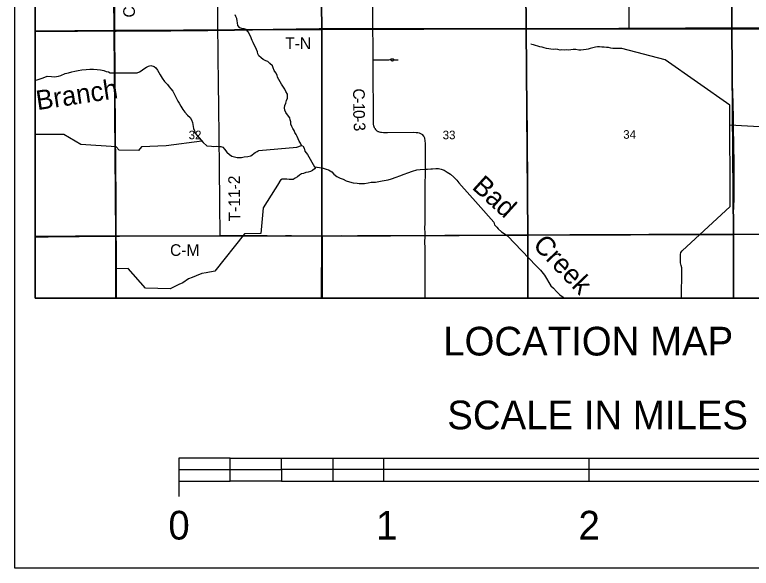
# Model space of a CAD drawing. Extents: x 0 to 34, y 0 to 22.
# Drawn here: x 23.417 to 27.01, y 14 to 16.699 of the extents above; entities that cross this region are included whole.
import ezdxf

# ---------------------------------------------------------------- set-up
doc = ezdxf.new("R2010")
doc.units = 0
for name, color, linetype in [('GM_X_County_Road', 7, 'Continuous'), ('GM_X_County_Road_Text', 7, 'Continuous'), ('GM_X_Minor_River', 7, 'Continuous'), ('GM_X_Minor_River_Text', 7, 'Continuous'), ('GM_X_Section', 7, 'Continuous'), ('GM_X_Section_Text', 7, 'Continuous'), ('GM_X_State_Route', 7, 'Continuous'), ('GM_X_Township_Road', 7, 'Continuous'), ('GM_X_Township_Road_Text', 7, 'Continuous'), ('GM_X_Township_Text', 7, 'Continuous'), ('SC_Scratch1', 7, 'Continuous'), ('SH_Data', 7, 'Continuous'), ('SH_Text', 7, 'Continuous')]:
    doc.layers.add(name, color=color, linetype=linetype)

msp = doc.modelspace()

# ---------------------------------------------------------------- linework, layer by layer
at = {"layer": 'GM_X_County_Road'}
for points in [[(23.9049, 16.6197), (23.9048, 16.6263), (23.9045, 16.6667), (23.903, 16.8346), (23.9026, 16.875), (23.9006, 17.0056), (23.8996, 17.0864), (23.8985, 17.161), (23.8971, 17.2885), (23.897, 17.3071), (23.8967, 17.3289), (23.8966, 17.3475), (23.8962, 17.3693), (23.8954, 17.4253), (23.8947, 17.4905), (23.8933, 17.6149), (23.8934, 17.6243)], [(25.1644, 16.6302), (25.1644, 16.6391), (25.1641, 16.6764), (25.1634, 16.7386), (25.1617, 16.8816), (25.1603, 16.9903), (25.1593, 17.1051), (25.1592, 17.1327), (25.1575, 17.2632), (25.157, 17.2847), (25.1567, 17.3248), (25.1562, 17.3557), (25.1558, 17.3991), (25.1547, 17.5016), (25.1535, 17.6025), (25.1534, 17.6272), (25.1534, 17.6295)], [(23.5167, 16.6173), (23.6476, 16.6186), (23.7222, 16.6189), (23.7998, 16.6205), (23.8216, 16.6207), (23.8778, 16.6199), (23.9049, 16.6197)], [(23.9049, 16.6197), (23.9108, 16.6197), (24.1779, 16.6213), (24.296, 16.6222), (24.3581, 16.6229), (24.4081, 16.6235)], [(23.9119, 15.6196), (23.9116, 15.647), (23.9112, 15.6874), (23.9112, 15.7247), (23.9108, 15.7931), (23.9093, 15.9766), (23.9087, 16.1134), (23.9081, 16.16), (23.9068, 16.3248), (23.9066, 16.3869), (23.9061, 16.446), (23.906, 16.4926), (23.9055, 16.5393), (23.9052, 16.6108), (23.9049, 16.6197)], [(24.4081, 16.6235), (24.4887, 16.6246), (24.5632, 16.6255), (24.7902, 16.6281), (24.9021, 16.6294), (25.0308, 16.6301), (25.034, 16.63), (25.0566, 16.6304), (25.1405, 16.6301), (25.1644, 16.6302)], [(25.1644, 16.6302), (25.2773, 16.6305), (25.3469, 16.6304), (25.4744, 16.6305), (25.6516, 16.6305), (25.7819, 16.6303), (25.8192, 16.63), (25.9122, 16.63)], [(25.1653, 16.4799), (25.1647, 16.5499), (25.1644, 16.6302)], [(25.9122, 16.63), (25.9249, 16.63), (26.1456, 16.6307), (26.1985, 16.6304), (26.3633, 16.6315), (26.4137, 16.6316)], [(26.4137, 16.6316), (26.4752, 16.6318), (26.6897, 16.6328), (26.9163, 16.6335)], [(26.9163, 16.6335), (26.9633, 16.6336), (27.0846, 16.6341), (27.3892, 16.6364), (27.4981, 16.6359), (27.6038, 16.635), (27.7748, 16.6349), (27.8618, 16.6351), (27.9219, 16.634)], [(25.1739, 16.1438), (25.1716, 16.1483), (25.1697, 16.1527), (25.1682, 16.1581), (25.1674, 16.165), (25.167, 16.177), (25.1669, 16.2173), (25.1666, 16.2671), (25.1659, 16.3666), (25.1656, 16.4319), (25.1653, 16.4799)], [(25.1739, 16.1438), (25.1768, 16.1397), (25.1789, 16.1375), (25.1835, 16.1335), (25.186, 16.1318), (25.1887, 16.1303), (25.1915, 16.1291), (25.1944, 16.1281), (25.2003, 16.1268), (25.2065, 16.126), (25.2158, 16.1254), (25.2345, 16.1251), (25.3627, 16.1257), (25.3751, 16.1255), (25.3834, 16.1245), (25.3904, 16.1233), (25.397, 16.1204), (25.4, 16.1185), (25.4055, 16.1148)], [(25.4183, 15.6229), (25.4182, 15.6345), (25.4181, 15.6594), (25.4182, 15.6811), (25.4185, 15.706), (25.4184, 15.7246), (25.4198, 16.0726), (25.4196, 16.082), (25.4191, 16.0882), (25.4179, 16.0942), (25.417, 16.0972), (25.4159, 16.1002), (25.414, 16.1045), (25.4117, 16.1078), (25.4055, 16.1148)], [(26.924, 15.6292), (26.9736, 15.6293), (27.0358, 15.6295), (27.0731, 15.6295), (27.1632, 15.6296), (27.2627, 15.6299), (27.328, 15.6301), (27.5799, 15.6306), (27.6389, 15.6309), (27.7571, 15.6311), (27.8751, 15.6306), (27.9275, 15.6305)], [(23.5167, 15.6163), (23.579, 15.6167), (23.6349, 15.6174), (23.7313, 15.6184), (23.8432, 15.6187), (23.893, 15.6191), (23.9119, 15.6196)], [(23.9119, 15.6196), (23.9272, 15.6199), (24.064, 15.6207), (24.1013, 15.6207), (24.2723, 15.6214), (24.4188, 15.6221)], [(23.9134, 15.3175), (23.9134, 15.4325), (23.9131, 15.4822), (23.9131, 15.504), (23.9126, 15.5786), (23.912, 15.6159), (23.9119, 15.6196)], [(24.4188, 15.6221), (24.4308, 15.6221), (24.5054, 15.622), (24.6484, 15.6219), (24.7262, 15.6214), (24.7355, 15.6216), (24.7386, 15.622), (24.7666, 15.6221), (24.9175, 15.6213)], [(24.9175, 15.6213), (24.9251, 15.6213), (25.0091, 15.6219), (25.0399, 15.6218), (25.0896, 15.6221), (25.1363, 15.6221), (25.1736, 15.6224), (25.2109, 15.6223), (25.2388, 15.6226), (25.301, 15.6228), (25.329, 15.6227), (25.3756, 15.623), (25.416, 15.6229), (25.4183, 15.6229)], [(25.4191, 15.3175), (25.4182, 15.5198), (25.4185, 15.5415), (25.4183, 15.5569), (25.4181, 15.5942), (25.4183, 15.6128), (25.4183, 15.6229)], [(25.4183, 15.6229), (25.4378, 15.6233), (25.5155, 15.6235), (25.5932, 15.6241), (25.7207, 15.6249), (25.7611, 15.6249), (25.8046, 15.6254), (25.8544, 15.6255), (25.9202, 15.6259)], [(25.9202, 15.6259), (25.9943, 15.6264), (26.0844, 15.6266), (26.1249, 15.6269), (26.2834, 15.6277), (26.3456, 15.6278), (26.4544, 15.6283), (26.5104, 15.6284), (26.6067, 15.6294), (26.6503, 15.6291), (26.6876, 15.6293), (26.7809, 15.6291), (26.8461, 15.629), (26.8897, 15.6292), (26.924, 15.6292)]]:
    msp.add_lwpolyline(points, dxfattribs=at)
at = {"layer": 'GM_X_Minor_River'}
msp.add_line((26.6687, 15.3175), (26.6717, 15.4543), dxfattribs=at)
for points in [[(24.816, 16.0607), (24.8101, 16.0733), (24.8045, 16.0832), (24.7997, 16.0939), (24.7946, 16.105), (24.7894, 16.1153), (24.783, 16.1252), (24.7793, 16.1347), (24.7726, 16.145), (24.7678, 16.1546), (24.7642, 16.166), (24.7631, 16.177), (24.761, 16.1873), (24.7584, 16.1968), (24.748, 16.2113), (24.739, 16.2231), (24.735, 16.2334), (24.7328, 16.2448), (24.7341, 16.2562), (24.7395, 16.2687), (24.7431, 16.2808), (24.7474, 16.2929), (24.7467, 16.3024), (24.7468, 16.3122), (24.7394, 16.3252), (24.7342, 16.3355), (24.7186, 16.36), (24.7119, 16.3722), (24.7056, 16.3828), (24.6992, 16.3939), (24.6963, 16.4049), (24.69, 16.4153), (24.6829, 16.4271), (24.6774, 16.4397), (24.6745, 16.4499), (24.6617, 16.4614), (24.652, 16.4703), (24.641, 16.4746), (24.6293, 16.4804), (24.6184, 16.4884), (24.6079, 16.498), (24.602, 16.5083), (24.6002, 16.5182), (24.5958, 16.5304), (24.591, 16.5415), (24.5843, 16.5529), (24.5798, 16.564), (24.5743, 16.5739), (24.5662, 16.5948), (24.5558, 16.6154), (24.5461, 16.6277), (24.5359, 16.6308), (24.5253, 16.632), (24.5154, 16.6356), (24.5057, 16.6474), (24.504, 16.6599), (24.5026, 16.6702), (24.4997, 16.6805), (24.496, 16.6908), (24.4915, 16.6984)], [(26.3791, 16.5341), (26.3666, 16.535), (26.3567, 16.5343), (26.3469, 16.5344), (26.3351, 16.5342), (26.3241, 16.5366), (26.3128, 16.5389), (26.3029, 16.5398), (26.2916, 16.5411), (26.281, 16.5415), (26.27, 16.542), (26.2594, 16.5421), (26.2499, 16.5407), (26.2373, 16.5378), (26.224, 16.5345), (26.2145, 16.532), (26.2043, 16.5298), (26.1906, 16.528), (26.1784, 16.5262), (26.1686, 16.5271), (26.1538, 16.5299), (26.1417, 16.53), (26.1288, 16.5279), (26.1193, 16.5264), (26.1076, 16.5273), (26.0981, 16.5263), (26.0863, 16.5279), (26.0768, 16.5269), (26.0655, 16.5296), (26.0538, 16.5309), (26.0431, 16.5298), (26.0318, 16.5315), (26.0219, 16.5331), (26.0102, 16.5351), (25.9992, 16.5371), (25.989, 16.5402), (25.9788, 16.5419), (25.9682, 16.5458), (25.958, 16.5485), (25.9482, 16.5528), (25.9376, 16.5548), (25.9361, 16.5567)], [(26.6724, 15.5473), (26.9061, 15.7639), (26.906, 16.258), (26.5892, 16.4797), (26.3791, 16.5341)], [(23.5167, 16.3793), (23.5262, 16.3816), (23.5551, 16.3919), (23.5745, 16.3993), (23.5954, 16.398), (23.6109, 16.3959), (23.631, 16.3999), (23.6417, 16.4032), (23.6623, 16.4121), (23.679, 16.4165), (23.6946, 16.4209), (23.7105, 16.4234), (23.7265, 16.4278), (23.7436, 16.4303), (23.7656, 16.4324), (23.7834, 16.4337), (23.8013, 16.4339), (23.8194, 16.4318), (23.835, 16.4305), (23.8512, 16.4269), (23.8625, 16.4223), (23.8743, 16.4199), (23.8822, 16.416), (23.9963, 16.4153), (24.0141, 16.4155), (24.0251, 16.4199), (24.0335, 16.4259), (24.0462, 16.4356), (24.0603, 16.4435), (24.0694, 16.4483), (24.0809, 16.4524), (24.0975, 16.4461), (24.1046, 16.4396), (24.1136, 16.4282), (24.1266, 16.4056), (24.1366, 16.3896), (24.1478, 16.3739), (24.1617, 16.3582), (24.1707, 16.3479), (24.1781, 16.3372), (24.1886, 16.3272), (24.1949, 16.3139), (24.2123, 16.2784), (24.2187, 16.2685), (24.2268, 16.2525), (24.2373, 16.2368), (24.2466, 16.2234), (24.2597, 16.2093), (24.2721, 16.1981), (24.2795, 16.1867), (24.2839, 16.1737), (24.2879, 16.1544), (24.2882, 16.1449), (24.293, 16.1327), (24.2974, 16.1224), (24.3359, 16.0757), (24.3536, 16.0604), (24.377, 16.0575), (24.3865, 16.0574), (24.3998, 16.0576), (24.4119, 16.0567), (24.4217, 16.0563), (24.4323, 16.0531), (24.4398, 16.0432), (24.451, 16.0294), (24.4641, 16.0171), (24.4766, 16.0094), (24.5015, 16.0035), (24.5224, 16.0033)], [(26.906, 16.1617), (27.2201, 16.1448), (27.2236, 16.1212), (27.3646, 16.1191)], [(24.3302, 16.0826), (24.1549, 16.0593), (24.0347, 16.0552), (24.0208, 16.0378), (23.9261, 16.0388), (23.9122, 16.0556), (23.7399, 16.0668), (23.6559, 16.1158), (23.5167, 16.1146)], [(24.5224, 16.0033), (24.536, 16.0058), (24.5546, 16.0083), (24.5691, 16.0119), (24.589, 16.0269), (24.5993, 16.0329), (24.605, 16.0362), (24.608, 16.0374), (24.7932, 16.053), (24.816, 16.0607), (24.8221, 16.0603), (24.8292, 16.0485), (24.8324, 16.0332), (24.8451, 16.0168), (24.8793, 15.958), (24.8922, 15.956), (24.9035, 15.9544), (24.9164, 15.9524), (24.9361, 15.9469), (24.9478, 15.9426), (24.964, 15.9325), (24.9741, 15.9222), (24.988, 15.9107), (25.0049, 15.9029), (25.0197, 15.8975), (25.0336, 15.8894), (25.0498, 15.8839), (25.068, 15.8799), (25.0873, 15.8771), (25.0975, 15.877), (25.1237, 15.8767), (25.1404, 15.8796), (25.1563, 15.8821), (25.1761, 15.8826), (25.1924, 15.8863), (25.2084, 15.8888), (25.2384, 15.8938), (25.2555, 15.8982), (25.2779, 15.9075), (25.2947, 15.9141), (25.3164, 15.9211), (25.3343, 15.9285), (25.3575, 15.937), (25.3788, 15.9429), (25.3944, 15.9446), (25.4213, 15.9467), (25.4308, 15.9458), (25.4459, 15.9476), (25.455, 15.9482), (25.471, 15.9492), (25.4846, 15.9487), (25.4975, 15.9467), (25.5115, 15.9416), (25.5261, 15.9312), (25.5423, 15.9212), (25.5585, 15.907), (25.5727, 15.8932), (25.5836, 15.8802), (25.6775, 15.7745), (25.7543, 15.6884), (25.7579, 15.6739), (25.7688, 15.6625), (25.7751, 15.6552), (25.7916, 15.6398), (25.8097, 15.6294), (25.8202, 15.6217), (25.9604, 15.4754), (25.9817, 15.4528), (26.0019, 15.4291), (26.0328, 15.3775), (26.0456, 15.366), (26.0598, 15.3503), (26.0759, 15.3339), (26.0917, 15.3212), (26.0974, 15.3175)], [(24.8873, 15.9568), (24.8792, 15.947), (24.8696, 15.9395), (24.8593, 15.9343), (24.8483, 15.9318), (24.8365, 15.9296), (24.8251, 15.9256), (24.8156, 15.9237), (24.8061, 15.9166), (24.7958, 15.9095), (24.7854, 15.9017), (24.7755, 15.8957), (24.7657, 15.8962), (24.7554, 15.8959), (24.7448, 15.8967), (24.7331, 15.8976), (24.7221, 15.8981), (24.7125, 15.8917), (24.7067, 15.8819), (24.7063, 15.8811)], [(24.7063, 15.8811), (24.6291, 15.7571), (24.6179, 15.632), (24.5371, 15.6309), (24.3921, 15.4479), (24.3507, 15.4407), (24.3295, 15.4371), (24.302, 15.4256), (24.2826, 15.4175), (24.2651, 15.4108), (24.2365, 15.3918), (24.217, 15.3836), (24.1938, 15.3724), (24.1743, 15.3632), (24.0553, 15.3666), (23.9704, 15.4616), (23.9112, 15.4599)], [(26.6717, 15.4543), (26.6718, 15.4642), (26.6678, 15.4768), (26.6649, 15.4886), (26.6642, 15.4988), (26.6647, 15.5087), (26.6645, 15.5197), (26.6638, 15.5299), (26.6662, 15.5398), (26.6724, 15.5473)]]:
    msp.add_lwpolyline(points, dxfattribs=at)
at = {"layer": 'GM_X_Section'}
for points in [[(23.5167, 17.6239), (23.5167, 16.6195), (23.9023, 16.6215), (23.8913, 17.6257)], [(23.8913, 17.6257), (24.9025, 17.6286), (24.9155, 16.6278), (23.9023, 16.6215)], [(24.9025, 17.6286), (25.9035, 17.634), (25.9123, 16.6303), (24.9155, 16.6278)], [(25.9035, 17.634), (26.9089, 17.6314), (26.9154, 16.6284), (25.9123, 16.6303)], [(26.9089, 17.6314), (27.9132, 17.6317), (27.9213, 16.6311), (26.9154, 16.6284)], [(23.5167, 16.6195), (23.5167, 15.617), (23.9096, 15.6204), (23.9023, 16.6215)], [(23.9023, 16.6215), (24.9155, 16.6278), (24.9143, 15.6197), (23.9096, 15.6204)], [(24.9155, 16.6278), (25.9123, 16.6303), (25.9206, 15.6247), (24.9143, 15.6197)], [(25.9123, 16.6303), (26.9154, 16.6284), (26.9227, 15.6274), (25.9206, 15.6247)], [(26.9154, 16.6284), (27.9213, 16.6311), (27.924, 15.6297), (26.9227, 15.6274)]]:
    msp.add_lwpolyline(points, close=True, dxfattribs=at)
for points in [[(23.9104, 15.3175), (23.9096, 15.6204), (23.5167, 15.617), (23.5167, 15.3175)], [(23.9104, 15.3175), (23.9096, 15.6204), (24.9143, 15.6197), (24.9138, 15.3175)], [(24.9138, 15.3175), (24.9143, 15.6197), (25.9206, 15.6247), (25.92, 15.3175)], [(25.92, 15.3175), (25.9206, 15.6247), (26.9227, 15.6274), (26.9227, 15.3175)], [(26.9227, 15.3175), (26.9227, 15.6274), (27.924, 15.6297), (27.924, 15.3175)]]:
    msp.add_lwpolyline(points, dxfattribs=at)
at = {"layer": 'GM_X_State_Route'}
for points in [[(26.9163, 16.6335), (26.9156, 16.7255), (26.9146, 16.8436), (26.9142, 16.94), (26.9118, 17.3037), (26.9114, 17.3877), (26.9108, 17.484), (26.9096, 17.635)], [(26.9255, 15.3175), (26.9254, 15.3298), (26.925, 15.3982), (26.9246, 15.5505), (26.924, 15.6292), (26.9238, 15.6593), (26.9233, 15.7091), (26.9235, 15.734), (26.9245, 15.762), (26.9262, 15.8023), (26.9268, 15.8365), (26.9266, 15.8862), (26.9257, 15.9826), (26.925, 16.0572), (26.9237, 16.1567), (26.923, 16.1908), (26.9211, 16.2685), (26.9192, 16.3151), (26.9182, 16.3649), (26.9178, 16.4053), (26.9171, 16.5172), (26.9163, 16.6335)]]:
    msp.add_lwpolyline(points, dxfattribs=at)
at = {"layer": 'GM_X_Township_Road'}
for points in [[(24.4081, 16.6235), (24.4075, 16.676), (24.4062, 16.8533), (24.4048, 17.015), (24.4037, 17.1363), (24.4026, 17.2452), (24.4015, 17.3353), (24.4012, 17.3819), (24.4003, 17.4286), (24.3988, 17.5779), (24.3987, 17.6214), (24.3986, 17.6265)], [(25.9122, 16.63), (25.9123, 16.6409), (25.9123, 16.6596), (25.9115, 16.7218), (25.9101, 16.8711), (25.91, 16.9022), (25.9093, 16.9426), (25.9083, 17.0576), (25.9074, 17.1447), (25.9066, 17.2349), (25.9057, 17.3002), (25.9057, 17.3127), (25.9055, 17.3345), (25.9051, 17.3842), (25.9042, 17.4744), (25.9031, 17.5584), (25.9024, 17.5895), (25.9022, 17.6144), (25.9024, 17.6299), (25.9025, 17.6344)], [(26.4137, 16.6316), (26.4139, 16.6383), (26.4144, 16.6539), (26.4141, 16.7253), (26.4132, 16.9147), (26.4124, 17.0514), (26.412, 17.1011), (26.4108, 17.2532), (26.4101, 17.3122), (26.4096, 17.3339), (26.4081, 17.4486), (26.4082, 17.4672), (26.4081, 17.4952), (26.407, 17.6225), (26.4066, 17.6348)], [(23.5167, 16.6173), (23.6476, 16.6186), (23.7222, 16.6189), (23.7998, 16.6205), (23.8216, 16.6207), (23.8778, 16.6199), (23.9049, 16.6197)], [(23.9049, 16.6197), (23.9108, 16.6197), (24.1779, 16.6213), (24.296, 16.6222), (24.3581, 16.6229), (24.4081, 16.6235)], [(24.4081, 16.6235), (24.4887, 16.6246), (24.5632, 16.6255), (24.7902, 16.6281), (24.9021, 16.6294), (25.0308, 16.6301), (25.034, 16.63), (25.0566, 16.6304), (25.1405, 16.6301), (25.1644, 16.6302)], [(24.4188, 15.6221), (24.4187, 15.6291), (24.4182, 15.6851), (24.4178, 15.7162), (24.4178, 15.7441), (24.4171, 15.7814), (24.4152, 15.9556), (24.4137, 16.1017), (24.4134, 16.1442), (24.4125, 16.2096), (24.4103, 16.4023), (24.4097, 16.4583), (24.4093, 16.4987), (24.4091, 16.536), (24.4081, 16.6235)], [(25.1644, 16.6302), (25.2773, 16.6305), (25.3469, 16.6304), (25.4744, 16.6305), (25.6516, 16.6305), (25.7819, 16.6303), (25.8192, 16.63), (25.9122, 16.63)], [(25.9122, 16.63), (25.9249, 16.63), (26.1456, 16.6307), (26.1985, 16.6304), (26.3633, 16.6315), (26.4137, 16.6316)], [(25.9202, 15.6259), (25.9201, 15.7555), (25.9196, 15.9078), (25.9189, 16.0601), (25.9184, 16.0942), (25.9165, 16.2744), (25.9156, 16.349), (25.9132, 16.5417), (25.9126, 16.6126), (25.9122, 16.63)], [(26.4137, 16.6316), (26.4752, 16.6318), (26.6897, 16.6328), (26.9163, 16.6335)], [(26.9163, 16.6335), (26.9633, 16.6336), (27.0846, 16.6341), (27.3892, 16.6364), (27.4981, 16.6359), (27.6038, 16.635), (27.7748, 16.6349), (27.8618, 16.6351), (27.9219, 16.634)], [(25.1653, 16.4799), (25.173, 16.4798), (25.2009, 16.4795), (25.2164, 16.4798), (25.2258, 16.48), (25.2413, 16.4798), (25.2473, 16.4801), (25.2497, 16.48)], [(25.2497, 16.48), (25.2506, 16.4811), (25.252, 16.4823), (25.2537, 16.4836), (25.2552, 16.4843), (25.2569, 16.4847), (25.259, 16.4848), (25.2608, 16.4847), (25.2621, 16.4841), (25.2633, 16.4835), (25.2644, 16.4824), (25.2649, 16.4812), (25.2651, 16.4796)], [(25.2497, 16.48), (25.2509, 16.4788), (25.2524, 16.4773), (25.2537, 16.4762), (25.2554, 16.4753), (25.2572, 16.4749), (25.2592, 16.4748), (25.2614, 16.4752), (25.2638, 16.4764), (25.2644, 16.4773), (25.2649, 16.4784), (25.2651, 16.4796)], [(25.2651, 16.4796), (25.2672, 16.4796), (25.2715, 16.4796), (25.2871, 16.4795)], [(24.9179, 15.3175), (24.9177, 15.3952), (24.918, 15.4698), (24.9176, 15.6098), (24.9175, 15.6213)], [(25.9208, 15.3175), (25.9207, 15.5224), (25.9206, 15.5628), (25.9202, 15.6156), (25.9202, 15.6259)]]:
    msp.add_lwpolyline(points, dxfattribs=at)
at = {"layer": 'GM_X_Township_Text'}
msp.add_lwpolyline([(27.0843, 16.6346), (26.9631, 16.6342), (26.916, 16.634), (26.6895, 16.6334), (26.4749, 16.6323), (26.4135, 16.6322), (26.363, 16.6321), (26.1982, 16.631), (26.1454, 16.6312), (25.9247, 16.6305), (25.912, 16.6305), (25.819, 16.6306), (25.7817, 16.6308), (25.6513, 16.631), (25.4741, 16.6311), (25.3467, 16.6309), (25.2771, 16.6311), (25.1642, 16.6308), (25.1403, 16.6307), (25.0564, 16.631), (25.0337, 16.6306), (25.0306, 16.6307), (24.9019, 16.6299), (24.79, 16.6287), (24.563, 16.6261), (24.4884, 16.6251), (24.4079, 16.6241), (24.3579, 16.6235), (24.2957, 16.6227), (24.1776, 16.6218), (23.9106, 16.6202), (23.9047, 16.6203), (23.8775, 16.6205), (23.8213, 16.6213), (23.7996, 16.6211), (23.7219, 16.6194), (23.6473, 16.6191), (23.5167, 16.6179), (23.5167, 15.3175)], dxfattribs=at)
at = {"layer": 'SC_Scratch1'}
msp.add_lwpolyline([(23.5167, 20.6789), (23.5167, 15.3175), (30.3167, 15.3175), (30.3167, 20.8109), (30.0181, 20.8047), (28.8862, 20.7941), (27.8891, 20.7835), (26.8843, 20.7634), (25.88, 20.7414), (25.1253, 20.7174), (23.8668, 20.6853)], close=True, dxfattribs=at)
at = {"layer": 'SH_Data'}
for p, q in [((24.4678, 14.5375), (24.2178, 14.5375)), ((24.2178, 14.5375), (24.2178, 14.4812)), ((24.4678, 14.5375), (24.7178, 14.5375)), ((24.4678, 14.4812), (24.4678, 14.5375)), ((24.7178, 14.4812), (24.7178, 14.5375)), ((24.7178, 14.5375), (24.9678, 14.5375)), ((24.9678, 14.5375), (25.2178, 14.5375)), ((24.9678, 14.5375), (24.9678, 14.4812)), ((25.2178, 14.4812), (25.2178, 14.5375)), ((25.2178, 14.5375), (26.2178, 14.5375)), ((26.2178, 14.5375), (26.2178, 14.4812)), ((26.2178, 14.5375), (27.2178, 14.5375)), ((24.2178, 14.4812), (24.2178, 14.35)), ((24.2178, 14.4812), (24.4678, 14.4812)), ((24.4678, 14.4812), (24.7178, 14.4812)), ((24.4678, 14.425), (24.4678, 14.4812)), ((24.7178, 14.4812), (24.7178, 14.425)), ((24.9678, 14.4812), (24.7178, 14.4812)), ((25.2178, 14.4812), (24.9678, 14.4812)), ((24.9678, 14.4812), (24.9678, 14.425)), ((25.2178, 14.425), (25.2178, 14.4812)), ((26.2178, 14.4812), (25.2178, 14.4812)), ((27.2178, 14.4812), (26.2178, 14.4812)), ((26.2178, 14.4812), (26.2178, 14.425)), ((24.2178, 14.425), (24.4678, 14.425)), ((24.7178, 14.425), (24.4678, 14.425)), ((24.7178, 14.425), (24.9678, 14.425)), ((24.9678, 14.425), (25.2178, 14.425)), ((25.2178, 14.425), (26.2178, 14.425)), ((26.2178, 14.425), (27.2178, 14.425))]:
    msp.add_line(p, q, dxfattribs=at)
for points in [[(23.4167, 21), (30.4167, 21), (30.4167, 14), (23.4167, 14)], [(23.5167, 20.9), (30.3167, 20.9), (30.3167, 15.3175), (23.5167, 15.3175)]]:
    msp.add_lwpolyline(points, close=True, dxfattribs=at)

# ---------------------------------------------------------------- texts
at = {"layer": 'GM_X_County_Road_Text'}
for s, height, rotation, p in [('C-12', 0.05682, 90.3442, (24.0031, 16.6857)), ('C', 0.0568, 270.2927, (25.0673, 16.3396)), ('-', 0.0568, 270.3251, (25.0676, 16.2929)), ('1', 0.0568, 270.403, (25.0677, 16.2695)), ('0', 0.0568, 270.7355, (25.0679, 16.2341)), ('3', 0.0568, 274.7362, (25.069, 16.1715)), ('-', 0.0568, 271.1164, (25.0684, 16.1987)), ('C-M', 0.05682, 0, (24.1744, 15.5231))]:
    msp.add_text(s, height=height, rotation=rotation, dxfattribs=at).set_placement(p)
at = {"layer": 'GM_X_Minor_River_Text'}
for s, height, rotation, p in [('Branch', 0.09477, 8.5399, (23.5277, 16.2337)), ('Bad', 0.09476, 317.8097, (25.6428, 15.8537)), ('Creek', 0.09476, 313.7065, (25.9397, 15.5724))]:
    msp.add_text(s, height=height, rotation=rotation, dxfattribs=at).set_placement(p)
at = {"layer": 'GM_X_Section_Text'}
for s, p in [('32', (24.2652, 16.0919)), ('33', (25.5044, 16.0919)), ('34', (26.3852, 16.0944))]:
    msp.add_text(s, height=0.04186, rotation=0, dxfattribs=at).set_placement(p)
at = {"layer": 'GM_X_Township_Road_Text'}
for s, rotation, p in [('T-N', 0, (24.736, 16.5316)), ('T-11-2', 90.4959, (24.5171, 15.6915))]:
    msp.add_text(s, height=0.05682, rotation=rotation, dxfattribs=at).set_placement(p)
at = {"layer": 'SH_Text'}
for s, p in [('LOCATION MAP', (25.5069, 15.0375)), ('SCALE IN MILES', (25.5268, 14.6775)), ('0', (24.1662, 14.14)), ('1', (25.1793, 14.14)), ('2', (26.1672, 14.14))]:
    msp.add_text(s, height=0.14, dxfattribs=at).set_placement(p)

doc.saveas('drawing.dxf')
